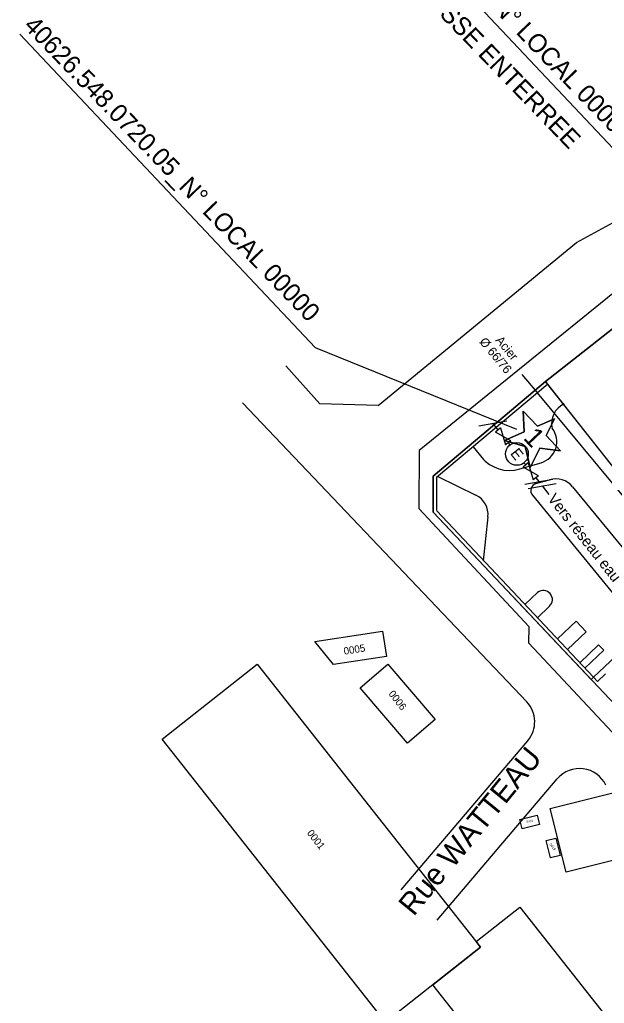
# Model space of a CAD drawing. Extents: x 704421 to 705059, y 7058908 to 7059523.
# Drawn here: x 704691.5 to 704771.8, y 7059261.6 to 7059396.7 of the extents above; entities that cross this region are included whole.
import ezdxf

# ---------------------------------------------------------------- set-up
doc = ezdxf.new("R2010")
doc.units = 0
for name, color, linetype in [('DH_HACHURE-MOTIF', 7, 'Continuous'), ('DH_TEXTE', 7, 'Continuous'), ('GEOSID_BATI_AERIEN _POLYGONE', 7, 'Continuous'), ('GEOSID_BATI_AERIEN_NUMERO', 7, 'Continuous'), ('GO_MUR_EXTERIEUR', 7, 'Continuous'), ('IMM_LIMITE PHYSIQUE', 7, 'Continuous'), ('LIB_08', 7, 'Continuous'), ('RES_EAU BASSE PRESSION', 7, 'Continuous'), ('RES_EAU BASSE PRESSION - EQUIP - TEXTE', 7, 'Continuous'), ('RES_INCENDIE - EQUIP - TEXTE', 7, 'Continuous'), ('SID_POLYLIGNES_BATI', 7, 'Continuous'), ('SID_POLYLIGNES_IMMEUBLE', 7, 'Continuous'), ('VOIRIE_BORDURE', 7, 'Continuous'), ('VOIRIE_ROUTE', 7, 'Continuous')]:
    doc.layers.add(name, color=color, linetype=linetype)

msp = doc.modelspace()

# ---------------------------------------------------------------- linework, layer by layer
at = {"layer": 'DH_HACHURE-MOTIF'}
msp.add_lwpolyline([(704764.01, 7059346.61), (704766.21, 7059343.82), (704794.39, 7059308.1), (704800.87, 7059313.21), (704807.43, 7059318.38), (704806.81, 7059319.17), (704777.07, 7059356.86), (704776.77, 7059357.24), (704763.73, 7059346.96), (704764.01, 7059346.61)], dxfattribs=at)
at = {"layer": 'GEOSID_BATI_AERIEN _POLYGONE'}
for points in [[(704732.06, 7059311.24), (704741.33, 7059312.67), (704741.91, 7059309.22), (704734.61, 7059308.12)], [(704711.1, 7059297.85), (704724.14, 7059308.13), (704754.79, 7059269.27), (704741.76, 7059258.99)], [(704738.29, 7059304.89), (704742.09, 7059308.14), (704748.59, 7059300.54), (704744.79, 7059297.29)], [(704764.38, 7059288.32), (704824.53, 7059303.35), (704825.56, 7059298.9), (704827.5, 7059299.38), (704828.65, 7059295.1), (704766.56, 7059279.59)], [(704760.22, 7059286.82), (704762.6, 7059287.41), (704762.92, 7059286.12), (704760.54, 7059285.52)], [(704763.83, 7059283.95), (704765.12, 7059284.27), (704765.72, 7059281.89), (704764.43, 7059281.57)], [(704748.24, 7059264.09), (704754.8, 7059269.27), (704754.18, 7059270.06), (704760.18, 7059274.79), (704800.56, 7059223.61), (704788, 7059213.7)]]:
    msp.add_lwpolyline(points, close=True, dxfattribs=at)
at = {"layer": 'GO_MUR_EXTERIEUR'}
for p, q in [((704763.73, 7059346.96), (704776.77, 7059357.24)), ((704794.39, 7059308.1), (704763.73, 7059346.96))]:
    msp.add_line(p, q, dxfattribs=at)
at = {"layer": 'IMM_LIMITE PHYSIQUE'}
for p, q in [((704763.74, 7059346.96), (704748.31, 7059333.98)), ((704764.02, 7059346.61), (704748.76, 7059333.77)), ((704748.31, 7059333.98), (704748.31, 7059329.03)), ((704748.76, 7059333.77), (704748.76, 7059329.24)), ((704748.31, 7059329.03), (704769.98, 7059306.06)), ((704748.78, 7059329.19), (704770.31, 7059306.37)), ((704770.31, 7059306.37), (704775.87, 7059311.62)), ((704770.86, 7059305.79), (704771.95, 7059306.81)), ((704770.31, 7059306.37), (704769.98, 7059306.06)), ((704770.31, 7059306.37), (704770.86, 7059305.79))]:
    msp.add_line(p, q, dxfattribs=at)
at = {"layer": 'LIB_08'}
for p, q in [((704762.61, 7059340.82), (704760.64, 7059342.91)), ((704760.64, 7059342.91), (704760.8, 7059340.04)), ((704764.97, 7059341.84), (704762.61, 7059340.82)), ((704763.82, 7059339.54), (704764.97, 7059341.84)), ((704760.8, 7059340.04), (704758.08, 7059338.87)), ((704765.78, 7059337.45), (704763.82, 7059339.54)), ((704761.6, 7059335.14), (704762.93, 7059337.79)), ((704762.93, 7059337.79), (704765.78, 7059337.45))]:
    msp.add_line(p, q, dxfattribs=at)
for points in [[(704733.91, 7059420.43), (704775.36, 7059376.5), (704782.12, 7059355.95)], [(704691.52, 7059394.66), (704732.1, 7059351.63), (704759.73, 7059340.42)], [(704758.08, 7059338.87), (704760.92, 7059338.02), (704760.92, 7059338.02)], [(704760.92, 7059338.02), (704760.92, 7059338.02), (704761.6, 7059335.14)]]:
    msp.add_lwpolyline(points, dxfattribs=at)
msp.add_lwpolyline([(704760.64, 7059342.91), (704762.61, 7059340.82), (704764.97, 7059341.84), (704763.82, 7059339.54), (704765.78, 7059337.45), (704762.93, 7059337.79), (704761.6, 7059335.14), (704760.92, 7059338.02), (704758.08, 7059338.87), (704760.8, 7059340.04)], close=True, dxfattribs=at)
at = {"layer": 'RES_EAU BASSE PRESSION'}
for p, q in [((704760.47, 7059347.93), (704762.55, 7059345.48)), ((704762.6, 7059345.41), (704794.07, 7059307.33)), ((704754.58, 7059340.87), (704758.4, 7059341.55)), ((704758.6, 7059338.54), (704758.83, 7059338.25)), ((704761, 7059335.5), (704760.76, 7059335.8)), ((704760.89, 7059332.88), (704764.71, 7059333.56)), ((704762.39, 7059333.74), (704762.8, 7059333.22))]:
    msp.add_line(p, q, dxfattribs=at)
at = {"layer": 'RES_EAU BASSE PRESSION - EQUIP - TEXTE'}
for p, q in [((704757.21, 7059340.31), (704756.49, 7059341.21)), ((704757.56, 7059340.58), (704756.85, 7059340.03)), ((704757.56, 7059340.58), (704758.25, 7059338.26)), ((704758.95, 7059338.82), (704756.85, 7059340.03)), ((704758.95, 7059338.82), (704758.25, 7059338.26)), ((704761.35, 7059335.78), (704760.64, 7059335.22)), ((704762.74, 7059334.01), (704760.64, 7059335.22)), ((704761.35, 7059335.78), (704762.04, 7059333.46)), ((704762.74, 7059334.01), (704762.04, 7059333.46)), ((704763.26, 7059332.63), (704764.19, 7059331.45))]:
    msp.add_line(p, q, dxfattribs=at)
msp.add_circle((704759.8, 7059337.02), 1.56, dxfattribs=at)
at = {"layer": 'RES_INCENDIE - EQUIP - TEXTE'}
msp.add_line((704761.35, 7059332.29), (704765.17, 7059332.97), dxfattribs=at)
at = {"layer": 'SID_POLYLIGNES_BATI'}
for p, q in [((704763.73, 7059346.96), (704776.77, 7059357.24)), ((704794.39, 7059308.1), (704763.73, 7059346.96))]:
    msp.add_line(p, q, dxfattribs=at)
at = {"layer": 'SID_POLYLIGNES_IMMEUBLE'}
for p, q in [((704748.31, 7059329.03), (704748.31, 7059333.98)), ((704837.52, 7059234.47), (704748.31, 7059329.03))]:
    msp.add_line(p, q, dxfattribs=at)
msp.add_lwpolyline([(704748.31, 7059333.98), (704763.73, 7059346.96), (704776.77, 7059357.24)], dxfattribs=at)
at = {"layer": 'VOIRIE_BORDURE'}
for p, q in [((704753.77, 7059337.98), (704755.19, 7059336.26)), ((704760.19, 7059334.95), (704763.11, 7059335.81)), ((704748.95, 7059333.94), (704754.17, 7059331.36)), ((704759.45, 7059334.74), (704759.45, 7059334.74)), ((704762.41, 7059332.94), (704764.29, 7059333.48)), ((704767.45, 7059332.5), (704778.41, 7059319.12)), ((704761.93, 7059331.35), (704774.55, 7059315.95)), ((704755.23, 7059322.35), (704755.83, 7059328.38)), ((704760.89, 7059316.35), (704762.63, 7059317.99)), ((704762.61, 7059314.53), (704764.26, 7059316.1)), ((704765.35, 7059311.62), (704767.93, 7059314.06)), ((704769.31, 7059312.61), (704767.93, 7059314.06)), ((704766.72, 7059310.17), (704769.31, 7059312.61)), ((704768.44, 7059308.35), (704771.02, 7059310.79)), ((704771.71, 7059310.06), (704771.02, 7059310.79)), ((704769.13, 7059307.62), (704771.71, 7059310.06))]:
    msp.add_line(p, q, dxfattribs=at)
for centre, radius, start, end in [((704767.56, 7059341.18), 3, 115.4761, 192.4737), ((704762.27, 7059338.69), 3, 286.3025, 37.942), ((704758.79, 7059339.75), 5, 219.5679, 286.3025), ((704765.12, 7059330.6), 3, 39.3307, 106.0656), ((704762.69, 7059331.98), 1, 106.0656, 219.3307), ((704752.84, 7059328.67), 3, 354.3306, 63.7442), ((704763.42, 7059317.02), 1.25, 312.1096, 129.3307)]:
    msp.add_arc(centre, radius, start, end, dxfattribs=at)
at = {"layer": 'VOIRIE_ROUTE'}
for p, q in [((704761.14, 7059302.96), (704722.11, 7059344.03)), ((704740.74, 7059343.69), (704732.72, 7059343.89)), ((704746.36, 7059337.47), (704746.32, 7059329.52)), ((704746.32, 7059329.52), (704761.49, 7059313.26)), ((704761.43, 7059311.05), (704761.49, 7059313.26)), ((704761.43, 7059311.05), (704781.89, 7059289.12)), ((704743.91, 7059277.15), (704761.29, 7059297.62)), ((704748.84, 7059272.97), (704765.34, 7059292.41))]:
    msp.add_line(p, q, dxfattribs=at)
for points in [[(704740.74, 7059343.69), (704767.97, 7059366.05), (704774, 7059369.35), (704782.46, 7059371.89), (704899.35, 7059389.72)], [(704900.6, 7059381.84), (704783.31, 7059363.81), (704773.95, 7059359.85), (704746.36, 7059337.47)], [(704732.72, 7059343.89), (704728.05, 7059349.13)]]:
    msp.add_lwpolyline(points, dxfattribs=at)
for centre, start, end in [((704758.24, 7059300.21), 319.6675, 43.547), ((704768.39, 7059289.82), 25.2763, 139.6675)]:
    msp.add_arc(centre, 4, start, end, dxfattribs=at)

# ---------------------------------------------------------------- texts
at = {"layer": 'DH_TEXTE'}
msp.add_text('Rue WATTEAU', height=3, rotation=50.7423, dxfattribs=at).set_placement((704745.62, 7059273.42))
at = {"layer": 'GEOSID_BATI_AERIEN_NUMERO'}
for s, height, rotation, p in [('0005', 1, 9.3307, (704736.09, 7059309.43)), ('0006', 1, 307.9879, (704742.11, 7059304.06)), ('0020', 0.295, 8.0308, (704761.13, 7059286.38)), ('0001', 1, 308.2727, (704730.91, 7059284.93)), ('0019', 0.346, 308.0308, (704764.24, 7059283.38))]:
    msp.add_text(s, height=height, rotation=rotation, dxfattribs=at).set_placement(p)
at = {"layer": 'LIB_08'}
for s, height, rotation, p in [('30000110341129_LOCAL N° 00001', 2.5, 313.3307, (704753.56, 7059423.84)), ('40626.548.0730.05_N° LOCAL 00000', 2.5, 313.9654, (704735, 7059420.29)), ('INCENDIE FOSSE ENTERREE', 2.5, 313.9654, (704734.08, 7059412.84)), ('40626.548.0720.05_N° LOCAL 00000', 2.5, 313.9654, (704691.93, 7059395.68)), ('1', 2.65, 313.3307, (704760.56, 7059339.13))]:
    msp.add_text(s, height=height, rotation=rotation, dxfattribs=at).set_placement(p)
at = {"layer": 'RES_EAU BASSE PRESSION - EQUIP - TEXTE'}
for s, height, rotation, p in [('%%C 66/76', 1.219, 309.5678, (704754.57, 7059352.39)), (' Acier', 1.219, 309.5678, (704756.49, 7059352.94)), ('E', 1.5, 308.2727, (704758.81, 7059337.06)), ('Vers réseau eau', 1.5, 308.2727, (704763.94, 7059330.84))]:
    msp.add_text(s, height=height, rotation=rotation, dxfattribs=at).set_placement(p)

doc.saveas('drawing.dxf')
